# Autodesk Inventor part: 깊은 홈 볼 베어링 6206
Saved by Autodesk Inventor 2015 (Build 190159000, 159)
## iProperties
Created: 2025-06
Part Number: 깊은 홈 볼 베어링 6206
Material: 일반
Document SubType Name: Modeling
Designer: 104
Density: 1 g/cm^3
Appearance: 기본값
Author: 104
Author: jhkim
Description: 깊은 그루부 볼 베어링
Creation Date: 2025-05-23
Sending System: Autodesk Inventor 2026
Preprocessor: ST-DEVELOPER v20.1
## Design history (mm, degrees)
node "깊은 홈 볼 베어링 62061"
body "Solid1"
node "Solid1_1"
node "Solid1_2"
node "Solid1_3"
node "Solid1_4"
node "Solid1_5"
node "Solid1_6"
node "Solid1_7"
node "Solid1_8"
node "Solid1_9"
node "Solid1_10"
node "기준1"
node "기준2"
node "기준3"
node "기준4"
node "기준5"
node "기준6"
node "기준7"
node "기준8"
node "기준9"
node "기준10"
node "기준11"
